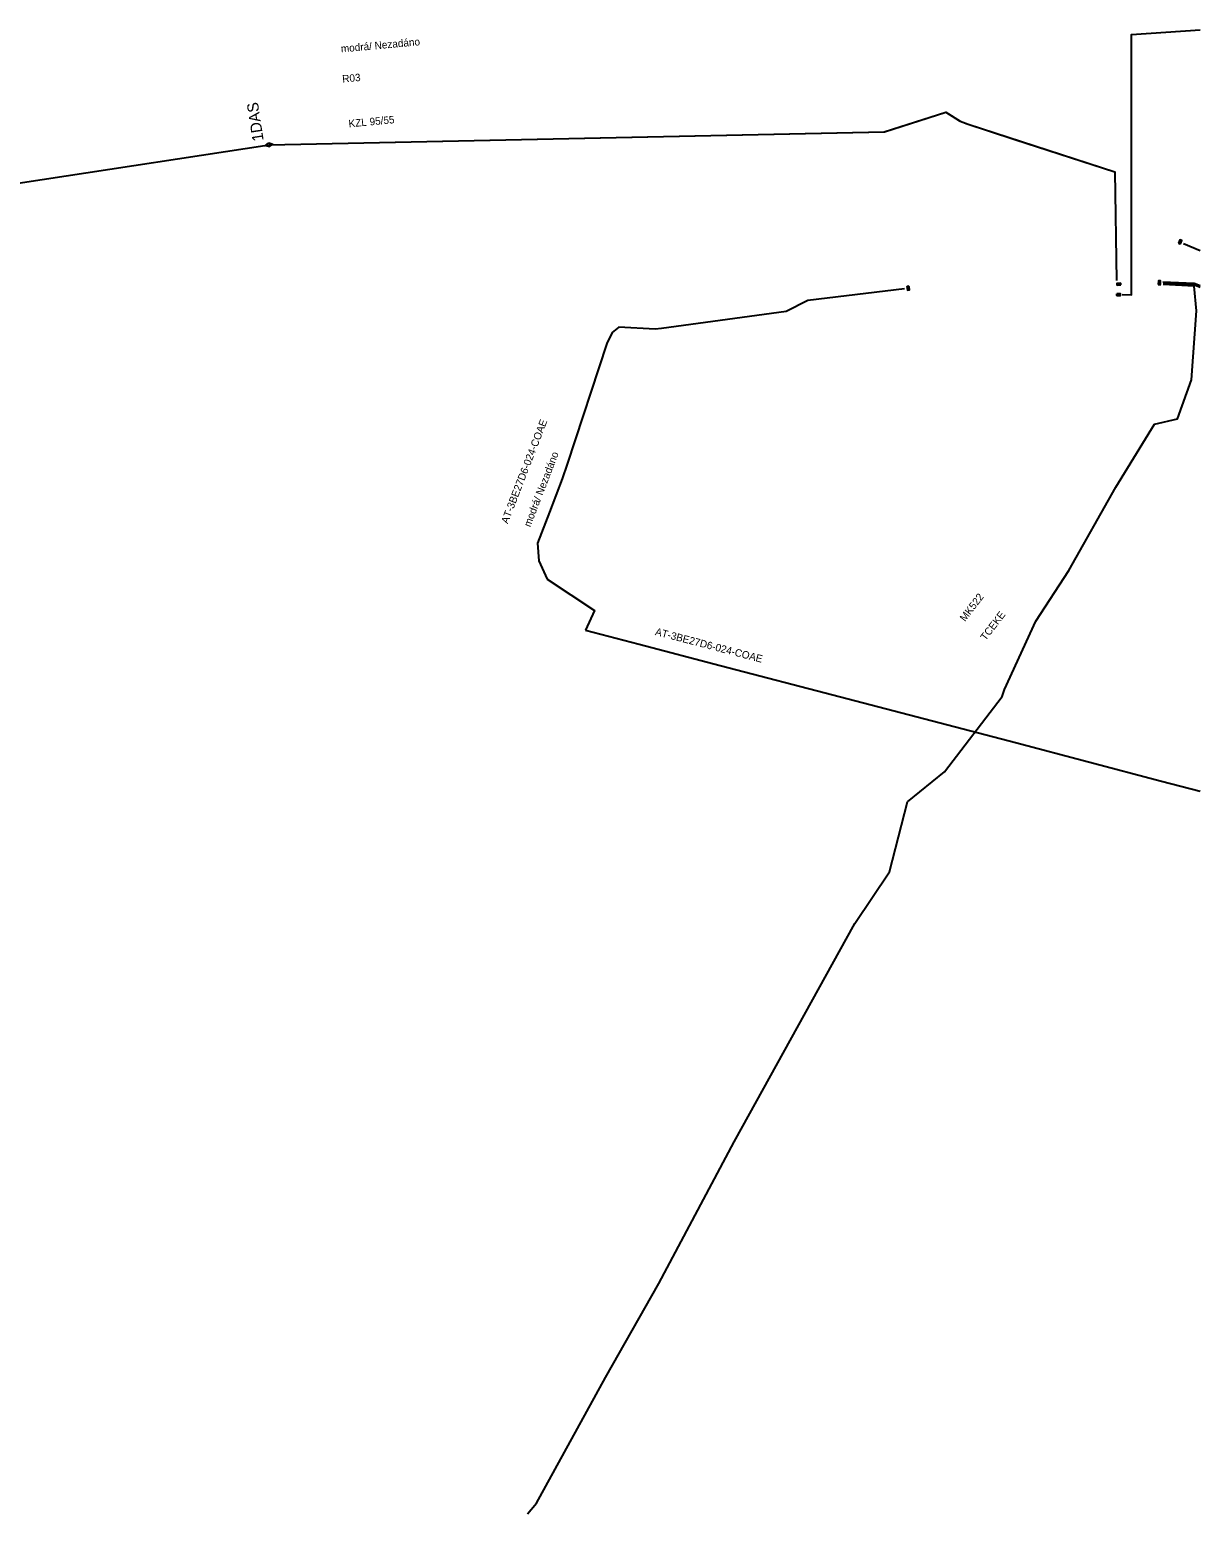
# Model space of a CAD drawing. Extents: x -763750 to -762497, y -1153000 to -1152057.
# Drawn here: x -762655.9 to -762500, y -1152879.5 to -1152681.8 of the extents above; entities that cross this region are included whole.
import ezdxf

# ---------------------------------------------------------------- set-up
doc = ezdxf.new("R2010")
doc.units = 0
for name, color, linetype in [('Vrstva 1', 7, 'Continuous'), ('Vrstva 10', 7, 'Continuous'), ('Vrstva 11', 7, 'Continuous'), ('Vrstva 2', 7, 'Continuous'), ('Vrstva 3', 7, 'Continuous'), ('Vrstva 4', 7, 'Continuous'), ('Vrstva 5', 7, 'Continuous'), ('Vrstva 6', 7, 'Continuous'), ('Vrstva 9', 7, 'Continuous')]:
    doc.layers.add(name, color=color, linetype=linetype)

msp = doc.modelspace()

# ---------------------------------------------------------------- linework, layer by layer
at = {"layer": 'Vrstva 1'}
for points in [[(-762624.455, -1152697.217), (-762624.004, -1152696.89)], [(-762624.455, -1152697.217), (-762623.918, -1152697.387)], [(-762624.004, -1152696.89), (-762623.467, -1152697.06)], [(-762623.918, -1152697.387), (-762623.467, -1152697.06)], [(-762581.85, -1152761.76), (-762574.72, -1152763.63), (-762563.91, -1152766.45), (-762547.9, -1152770.63), (-762524.6, -1152776.74), (-762505.15, -1152781.89), (-762500, -1152783.22)]]:
    msp.add_lwpolyline(points, dxfattribs=at)
at = {"layer": 'Vrstva 11'}
msp.add_lwpolyline([(-763559.31, -1153000), (-763291.13, -1152798.96), (-762805.36, -1152724.84), (-762623.96, -1152697.14)], dxfattribs=at)
at = {"layer": 'Vrstva 3'}
for points in [[(-762510.4, -1152717.08), (-762509.15, -1152717.12), (-762509.15, -1152682.46), (-762500, -1152681.82)], [(-762623.96, -1152697.14), (-762542.06, -1152695.41), (-762533.87, -1152692.8), (-762531.99, -1152694.01), (-762530.93, -1152694.42), (-762511.38, -1152700.76), (-762511.14, -1152715.22)], [(-762502.24, -1152710.27), (-762500, -1152711.24)], [(-762539.38, -1152716.3), (-762552.24, -1152717.87), (-762555.12, -1152719.34), (-762571.74, -1152721.59), (-762572.6, -1152721.68), (-762577.42, -1152721.41), (-762578.29, -1152722.13), (-762579.01, -1152723.59), (-762584.31, -1152739.67), (-762584.97, -1152741.62), (-762586.67, -1152746.06), (-762588.23, -1152750.18), (-762588.05, -1152752.55), (-762586.94, -1152754.97), (-762580.68, -1152759.16), (-762581.85, -1152761.76)]]:
    msp.add_lwpolyline(points, dxfattribs=at)
at = {"layer": 'Vrstva 5'}
for points in [[(-762510.4, -1152717.08), (-762509.15, -1152717.12), (-762509.15, -1152682.46), (-762500, -1152681.82)], [(-762623.96, -1152697.14), (-762542.07, -1152695.41), (-762533.87, -1152692.79), (-762532.05, -1152693.97), (-762531.18, -1152694.33), (-762524.7, -1152696.44), (-762511.4, -1152700.74), (-762511.14, -1152715.22)], [(-762502.24, -1152710.27), (-762500, -1152711.24)], [(-762539.38, -1152716.3), (-762552.24, -1152717.87), (-762555.12, -1152719.34), (-762571.74, -1152721.59), (-762572.6, -1152721.68), (-762577.42, -1152721.41), (-762578.29, -1152722.13), (-762579.01, -1152723.59), (-762584.31, -1152739.67), (-762584.97, -1152741.62), (-762586.67, -1152746.06), (-762588.23, -1152750.18), (-762588.05, -1152752.55), (-762586.94, -1152754.97), (-762580.68, -1152759.16), (-762581.85, -1152761.76)]]:
    msp.add_lwpolyline(points, dxfattribs=at)
at = {"layer": 'Vrstva 9'}
for p, q in [((-762502.873, -1152710.244), (-762502.696, -1152709.827)), ((-762502.868, -1152710.246), (-762502.691, -1152709.829)), ((-762502.863, -1152710.247), (-762502.686, -1152709.83)), ((-762502.859, -1152710.249), (-762502.682, -1152709.832)), ((-762502.854, -1152710.251), (-762502.677, -1152709.834)), ((-762502.85, -1152710.253), (-762502.672, -1152709.836)), ((-762502.845, -1152710.255), (-762502.668, -1152709.838)), ((-762502.84, -1152710.257), (-762502.663, -1152709.84)), ((-762502.836, -1152710.259), (-762502.659, -1152709.842)), ((-762502.831, -1152710.261), (-762502.654, -1152709.844)), ((-762502.827, -1152710.263), (-762502.649, -1152709.846)), ((-762502.822, -1152710.265), (-762502.645, -1152709.848)), ((-762502.817, -1152710.267), (-762502.64, -1152709.85)), ((-762502.813, -1152710.269), (-762502.636, -1152709.852)), ((-762502.808, -1152710.271), (-762502.631, -1152709.854)), ((-762502.803, -1152710.273), (-762502.626, -1152709.856)), ((-762502.799, -1152710.275), (-762502.622, -1152709.858)), ((-762502.794, -1152710.277), (-762502.617, -1152709.86)), ((-762502.79, -1152710.279), (-762502.613, -1152709.862)), ((-762502.785, -1152710.281), (-762502.608, -1152709.864)), ((-762502.78, -1152710.283), (-762502.603, -1152709.866)), ((-762502.776, -1152710.285), (-762502.599, -1152709.868)), ((-762502.771, -1152710.287), (-762502.594, -1152709.87)), ((-762502.767, -1152710.289), (-762502.59, -1152709.871)), ((-762502.762, -1152710.29), (-762502.585, -1152709.873)), ((-762502.757, -1152710.292), (-762502.58, -1152709.875)), ((-762502.753, -1152710.294), (-762502.576, -1152709.877)), ((-762502.748, -1152710.296), (-762502.571, -1152709.879)), ((-762502.744, -1152710.298), (-762502.567, -1152709.881)), ((-762502.739, -1152710.3), (-762502.562, -1152709.883)), ((-762502.734, -1152710.302), (-762502.557, -1152709.885)), ((-762502.73, -1152710.304), (-762502.553, -1152709.887)), ((-762502.725, -1152710.306), (-762502.548, -1152709.889)), ((-762502.721, -1152710.308), (-762502.544, -1152709.891)), ((-762502.716, -1152710.31), (-762502.539, -1152709.893)), ((-762502.711, -1152710.312), (-762502.534, -1152709.895)), ((-762502.707, -1152710.314), (-762502.53, -1152709.897)), ((-762502.702, -1152710.316), (-762502.525, -1152709.899)), ((-762502.698, -1152710.318), (-762502.521, -1152709.901)), ((-762502.693, -1152710.32), (-762502.516, -1152709.903)), ((-762539.011, -1152716.027), (-762538.956, -1152716.477)), ((-762539.006, -1152716.026), (-762538.951, -1152716.476)), ((-762539.001, -1152716.026), (-762538.946, -1152716.475)), ((-762538.996, -1152716.025), (-762538.941, -1152716.475)), ((-762538.991, -1152716.025), (-762538.936, -1152716.474)), ((-762538.986, -1152716.024), (-762538.931, -1152716.474)), ((-762538.981, -1152716.023), (-762538.926, -1152716.473)), ((-762538.976, -1152716.023), (-762538.921, -1152716.472)), ((-762538.971, -1152716.022), (-762538.916, -1152716.472)), ((-762538.966, -1152716.022), (-762538.911, -1152716.471)), ((-762538.961, -1152716.021), (-762538.906, -1152716.471)), ((-762538.957, -1152716.02), (-762538.901, -1152716.47)), ((-762538.952, -1152716.02), (-762538.896, -1152716.469)), ((-762538.947, -1152716.019), (-762538.891, -1152716.469)), ((-762538.942, -1152716.018), (-762538.886, -1152716.468)), ((-762538.937, -1152716.018), (-762538.881, -1152716.468)), ((-762538.932, -1152716.017), (-762538.877, -1152716.467)), ((-762538.927, -1152716.017), (-762538.872, -1152716.466)), ((-762538.922, -1152716.016), (-762538.867, -1152716.466)), ((-762538.917, -1152716.015), (-762538.862, -1152716.465)), ((-762538.912, -1152716.015), (-762538.857, -1152716.465)), ((-762538.907, -1152716.014), (-762538.852, -1152716.464)), ((-762538.902, -1152716.014), (-762538.847, -1152716.463)), ((-762538.897, -1152716.013), (-762538.842, -1152716.463)), ((-762538.892, -1152716.012), (-762538.837, -1152716.462)), ((-762538.887, -1152716.012), (-762538.832, -1152716.461)), ((-762538.882, -1152716.011), (-762538.827, -1152716.461)), ((-762538.877, -1152716.011), (-762538.822, -1152716.46)), ((-762538.872, -1152716.01), (-762538.817, -1152716.46)), ((-762538.867, -1152716.009), (-762538.812, -1152716.459)), ((-762538.862, -1152716.009), (-762538.807, -1152716.458)), ((-762538.857, -1152716.008), (-762538.802, -1152716.458)), ((-762538.852, -1152716.008), (-762538.797, -1152716.457)), ((-762538.847, -1152716.007), (-762538.792, -1152716.457)), ((-762538.842, -1152716.006), (-762538.787, -1152716.456)), ((-762538.837, -1152716.006), (-762538.782, -1152716.455)), ((-762538.832, -1152716.005), (-762538.777, -1152716.455)), ((-762538.827, -1152716.004), (-762538.772, -1152716.454)), ((-762538.823, -1152716.004), (-762538.767, -1152716.454)), ((-762538.818, -1152716.003), (-762538.762, -1152716.453)), ((-762510.633, -1152715.587), (-762511.084, -1152715.626)), ((-762510.632, -1152715.592), (-762511.083, -1152715.631)), ((-762510.632, -1152715.597), (-762511.083, -1152715.636)), ((-762510.631, -1152715.602), (-762511.083, -1152715.641)), ((-762510.631, -1152715.607), (-762511.082, -1152715.646)), ((-762510.63, -1152715.612), (-762511.082, -1152715.651)), ((-762510.63, -1152715.617), (-762511.081, -1152715.656)), ((-762510.629, -1152715.622), (-762511.081, -1152715.661)), ((-762510.629, -1152715.627), (-762511.08, -1152715.666)), ((-762510.629, -1152715.632), (-762511.08, -1152715.671)), ((-762510.628, -1152715.637), (-762511.079, -1152715.676)), ((-762510.628, -1152715.641), (-762511.079, -1152715.681)), ((-762510.627, -1152715.646), (-762511.079, -1152715.686)), ((-762510.627, -1152715.651), (-762511.078, -1152715.691)), ((-762510.626, -1152715.656), (-762511.078, -1152715.696)), ((-762510.626, -1152715.661), (-762511.077, -1152715.701)), ((-762510.626, -1152715.666), (-762511.077, -1152715.706)), ((-762510.625, -1152715.671), (-762511.076, -1152715.711)), ((-762510.625, -1152715.676), (-762511.076, -1152715.716)), ((-762510.624, -1152715.681), (-762511.076, -1152715.721)), ((-762510.624, -1152715.686), (-762511.075, -1152715.726)), ((-762510.623, -1152715.691), (-762511.075, -1152715.731)), ((-762510.623, -1152715.696), (-762511.074, -1152715.736)), ((-762510.623, -1152715.701), (-762511.074, -1152715.741)), ((-762510.622, -1152715.706), (-762511.073, -1152715.746)), ((-762510.622, -1152715.711), (-762511.073, -1152715.751)), ((-762510.621, -1152715.716), (-762511.073, -1152715.756)), ((-762510.621, -1152715.721), (-762511.072, -1152715.761)), ((-762510.62, -1152715.726), (-762511.072, -1152715.766)), ((-762510.62, -1152715.731), (-762511.071, -1152715.771)), ((-762510.619, -1152715.736), (-762511.071, -1152715.776)), ((-762510.619, -1152715.741), (-762511.07, -1152715.781)), ((-762510.619, -1152715.746), (-762511.07, -1152715.786)), ((-762510.618, -1152715.751), (-762511.069, -1152715.791)), ((-762510.618, -1152715.756), (-762511.069, -1152715.796)), ((-762510.617, -1152715.761), (-762511.069, -1152715.801)), ((-762510.617, -1152715.766), (-762511.068, -1152715.805)), ((-762510.616, -1152715.771), (-762511.068, -1152715.81)), ((-762510.616, -1152715.776), (-762511.067, -1152715.815)), ((-762510.616, -1152715.781), (-762511.067, -1152715.82)), ((-762505.563, -1152715.742), (-762505.539, -1152715.289)), ((-762505.558, -1152715.742), (-762505.534, -1152715.29)), ((-762505.553, -1152715.742), (-762505.529, -1152715.29)), ((-762505.548, -1152715.743), (-762505.524, -1152715.29)), ((-762505.543, -1152715.743), (-762505.519, -1152715.29)), ((-762505.538, -1152715.743), (-762505.514, -1152715.291)), ((-762505.533, -1152715.743), (-762505.509, -1152715.291)), ((-762505.528, -1152715.744), (-762505.504, -1152715.291)), ((-762505.523, -1152715.744), (-762505.499, -1152715.291)), ((-762505.518, -1152715.744), (-762505.494, -1152715.292)), ((-762505.513, -1152715.744), (-762505.489, -1152715.292)), ((-762505.508, -1152715.745), (-762505.484, -1152715.292)), ((-762505.503, -1152715.745), (-762505.479, -1152715.292)), ((-762505.498, -1152715.745), (-762505.474, -1152715.293)), ((-762505.493, -1152715.745), (-762505.469, -1152715.293)), ((-762505.488, -1152715.746), (-762505.464, -1152715.293)), ((-762505.483, -1152715.746), (-762505.459, -1152715.293)), ((-762505.478, -1152715.746), (-762505.454, -1152715.294)), ((-762505.473, -1152715.746), (-762505.449, -1152715.294)), ((-762505.468, -1152715.747), (-762505.444, -1152715.294)), ((-762505.463, -1152715.747), (-762505.439, -1152715.295)), ((-762505.458, -1152715.747), (-762505.434, -1152715.295)), ((-762505.453, -1152715.747), (-762505.429, -1152715.295)), ((-762505.448, -1152715.748), (-762505.424, -1152715.295)), ((-762505.443, -1152715.748), (-762505.419, -1152715.296)), ((-762505.438, -1152715.748), (-762505.414, -1152715.296)), ((-762505.433, -1152715.749), (-762505.409, -1152715.296)), ((-762505.428, -1152715.749), (-762505.404, -1152715.296)), ((-762505.423, -1152715.749), (-762505.399, -1152715.297)), ((-762505.418, -1152715.749), (-762505.394, -1152715.297)), ((-762505.413, -1152715.75), (-762505.389, -1152715.297)), ((-762505.408, -1152715.75), (-762505.384, -1152715.297)), ((-762505.403, -1152715.75), (-762505.379, -1152715.298)), ((-762505.398, -1152715.75), (-762505.374, -1152715.298)), ((-762505.393, -1152715.751), (-762505.369, -1152715.298)), ((-762505.388, -1152715.751), (-762505.364, -1152715.298)), ((-762505.383, -1152715.751), (-762505.359, -1152715.299)), ((-762505.378, -1152715.751), (-762505.354, -1152715.299)), ((-762505.373, -1152715.752), (-762505.349, -1152715.299)), ((-762505.368, -1152715.752), (-762505.344, -1152715.3)), ((-762511.107, -1152716.999), (-762510.654, -1152716.999)), ((-762511.107, -1152717.004), (-762510.654, -1152717.004)), ((-762511.107, -1152717.009), (-762510.654, -1152717.009)), ((-762511.107, -1152717.014), (-762510.654, -1152717.014)), ((-762511.107, -1152717.019), (-762510.654, -1152717.019)), ((-762511.107, -1152717.024), (-762510.654, -1152717.024)), ((-762511.107, -1152717.029), (-762510.654, -1152717.029)), ((-762511.107, -1152717.034), (-762510.654, -1152717.034)), ((-762511.107, -1152717.039), (-762510.654, -1152717.039)), ((-762511.107, -1152717.044), (-762510.654, -1152717.044)), ((-762511.107, -1152717.049), (-762510.654, -1152717.049)), ((-762511.107, -1152717.054), (-762510.654, -1152717.054)), ((-762511.107, -1152717.059), (-762510.654, -1152717.059)), ((-762511.107, -1152717.064), (-762510.654, -1152717.064)), ((-762511.107, -1152717.069), (-762510.654, -1152717.069)), ((-762511.107, -1152717.074), (-762510.654, -1152717.074)), ((-762511.107, -1152717.079), (-762510.654, -1152717.079)), ((-762511.107, -1152717.084), (-762510.654, -1152717.084)), ((-762511.107, -1152717.089), (-762510.654, -1152717.089)), ((-762511.107, -1152717.094), (-762510.654, -1152717.094)), ((-762511.107, -1152717.099), (-762510.654, -1152717.099)), ((-762511.107, -1152717.104), (-762510.654, -1152717.104)), ((-762511.107, -1152717.109), (-762510.654, -1152717.109)), ((-762511.107, -1152717.114), (-762510.654, -1152717.114)), ((-762511.107, -1152717.119), (-762510.654, -1152717.119)), ((-762511.107, -1152717.124), (-762510.654, -1152717.124)), ((-762511.107, -1152717.129), (-762510.654, -1152717.129)), ((-762511.107, -1152717.134), (-762510.654, -1152717.134)), ((-762511.107, -1152717.139), (-762510.654, -1152717.139)), ((-762511.107, -1152717.144), (-762510.654, -1152717.144)), ((-762511.107, -1152717.149), (-762510.654, -1152717.149)), ((-762511.107, -1152717.154), (-762510.654, -1152717.154)), ((-762511.107, -1152717.159), (-762510.654, -1152717.159)), ((-762511.107, -1152717.164), (-762510.654, -1152717.164)), ((-762511.107, -1152717.169), (-762510.654, -1152717.169)), ((-762511.107, -1152717.174), (-762510.654, -1152717.174)), ((-762511.107, -1152717.179), (-762510.654, -1152717.179)), ((-762511.107, -1152717.184), (-762510.654, -1152717.184)), ((-762511.107, -1152717.189), (-762510.654, -1152717.189)), ((-762511.107, -1152717.194), (-762510.654, -1152717.194))]:
    msp.add_line(p, q, dxfattribs=at)
for points in [[(-762502.907, -1152710.254), (-762502.677, -1152710.352), (-762502.482, -1152709.892), (-762502.712, -1152709.794)], [(-762502.877, -1152710.242), (-762502.7, -1152709.825), (-762502.513, -1152709.904), (-762502.69, -1152710.321)], [(-762538.793, -1152715.976), (-762539.041, -1152716.007), (-762538.98, -1152716.503), (-762538.732, -1152716.473)], [(-762538.813, -1152716.003), (-762538.758, -1152716.452), (-762538.959, -1152716.477), (-762539.014, -1152716.027)], [(-762510.59, -1152715.807), (-762510.611, -1152715.558), (-762511.109, -1152715.601), (-762511.088, -1152715.85)], [(-762510.615, -1152715.785), (-762511.066, -1152715.825), (-762511.084, -1152715.623), (-762510.633, -1152715.584)], [(-762505.592, -1152715.764), (-762505.342, -1152715.777), (-762505.316, -1152715.278), (-762505.566, -1152715.265)], [(-762505.567, -1152715.741), (-762505.544, -1152715.289), (-762505.341, -1152715.3), (-762505.365, -1152715.752)], [(-762511.131, -1152716.971), (-762511.131, -1152717.221), (-762510.631, -1152717.221), (-762510.631, -1152716.971)], [(-762511.107, -1152716.995), (-762510.654, -1152716.995), (-762510.654, -1152717.197), (-762511.107, -1152717.197)]]:
    msp.add_lwpolyline(points, close=True, dxfattribs=at)
for points in [[(-762502.877, -1152710.242), (-762502.69, -1152710.321)], [(-762589.59, -1152879.42), (-762588.38, -1152878.01), (-762579.21, -1152861.28), (-762572.11, -1152848.73), (-762562.06, -1152829.89), (-762545.99, -1152800.8), (-762541.39, -1152793.93), (-762538.97, -1152784.62), (-762534.08, -1152780.64), (-762526.4, -1152770.61), (-762526.07, -1152769.65), (-762521.9, -1152760.56), (-762517.51, -1152753.82), (-762511.24, -1152742.74), (-762506.1, -1152734.34), (-762503.03, -1152733.64), (-762501.19, -1152728.44), (-762500.51, -1152719.27), (-762500.83, -1152715.97), (-762504.95, -1152715.73)], [(-762538.813, -1152716.003), (-762539.015, -1152716.027)], [(-762510.615, -1152715.785), (-762510.633, -1152715.583)], [(-762505.567, -1152715.742), (-762505.365, -1152715.752)], [(-762504.97, -1152715.37), (-762500.82, -1152715.58), (-762500, -1152715.88)], [(-762504.96, -1152715.54), (-762500.89, -1152715.76), (-762500, -1152716.1)], [(-762511.107, -1152716.995), (-762511.107, -1152717.198)]]:
    msp.add_lwpolyline(points, dxfattribs=at)

# ---------------------------------------------------------------- texts
at = {"layer": 'Vrstva 10'}
for s, p in [('MK522', (-762531.33, -1152760.69)), ('TCEKE', (-762528.58, -1152763.24))]:
    msp.add_text(s, height=0.9943, rotation=52.55861, dxfattribs=at).set_placement(p)
at = {"layer": 'Vrstva 2'}
for s, height, rotation, p in [('1DAS ', 1.4914, 98.67964, (-762624.7, -1152696.55)), ('AT-3BE27D6-024-COAE', 0.99429, 345.40286, (-762572.66, -1152762.4))]:
    msp.add_text(s, height=height, rotation=rotation, dxfattribs=at).set_placement(p)
at = {"layer": 'Vrstva 4'}
for s, height, rotation, p in [('R03', 0.9943, 5.25848, (-762614.2, -1152688.87)), ('KZL 95/55', 0.9943, 5.25848, (-762613.36, -1152694.83)), ('AT-3BE27D6-024-COAE', 0.99428, 68.94431, (-762592.21, -1152747.67))]:
    msp.add_text(s, height=height, rotation=rotation, dxfattribs=at).set_placement(p)
at = {"layer": 'Vrstva 6'}
for height, rotation, p in [(0.99429, 5.25848, (-762614.75, -1152684.89)), (0.99428, 68.94431, (-762589.34, -1152748.45))]:
    msp.add_text(' modrá/ Nezadáno', height=height, rotation=rotation, dxfattribs=at).set_placement(p)

doc.saveas('drawing.dxf')
